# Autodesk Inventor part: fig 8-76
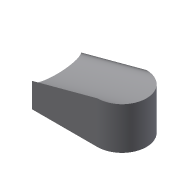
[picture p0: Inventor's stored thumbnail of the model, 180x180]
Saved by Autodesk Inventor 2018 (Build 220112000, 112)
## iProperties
Shininess: 77.0
Length Units: 11269
Angle Units: 11279
Time Units: 11290
Mass Units: 11283
Length Display Precision: 3
Angle Display Precision: 2
Created: 2002-01
Part Number: fig 8-76
Document SubType Name: Modeling
Designer: ***
Density: 1 g/cm^3
Material: Generic
Appearance: Default
Density: 0.0
Volumn: 0.0
Area: 0.0
PropertySet Name: Model Information
Control State: 0
Master: False
Checked Out: False
Author: ***
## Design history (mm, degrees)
sketch "Sketch2"
  geometry: L1 (-25.088, 14.941)-(-25.088, -14.161); L2 (-25.088, -14.161)-(13.729, -14.161); L3 (13.729, 14.941)-(-25.088, 14.941); A1 r 14.551 centre (13.729, 0.39) between (13.729, -14.161) and (13.729, 14.941)
  constraints: 6 end point, 2 point on circle, 2 tangent, 1 centre point, 1 parallel, 1 perpendicular, 1 vertical
extrude "Extrusion2" new body sketch "Sketch2" distance "d6" = 25; taper "d7" = 0 deg
feature "FaceDraft9" dims angle "d15" = 15 deg
body "Solid1"
